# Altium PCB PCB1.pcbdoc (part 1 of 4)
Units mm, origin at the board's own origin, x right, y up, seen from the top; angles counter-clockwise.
Board outline 94.87 x 122.3 mm, 4 copper layers (Top Layer, Inner1, Inner2, Bottom Layer); 129 components, 127 nets, 714 pads, 326 vias.
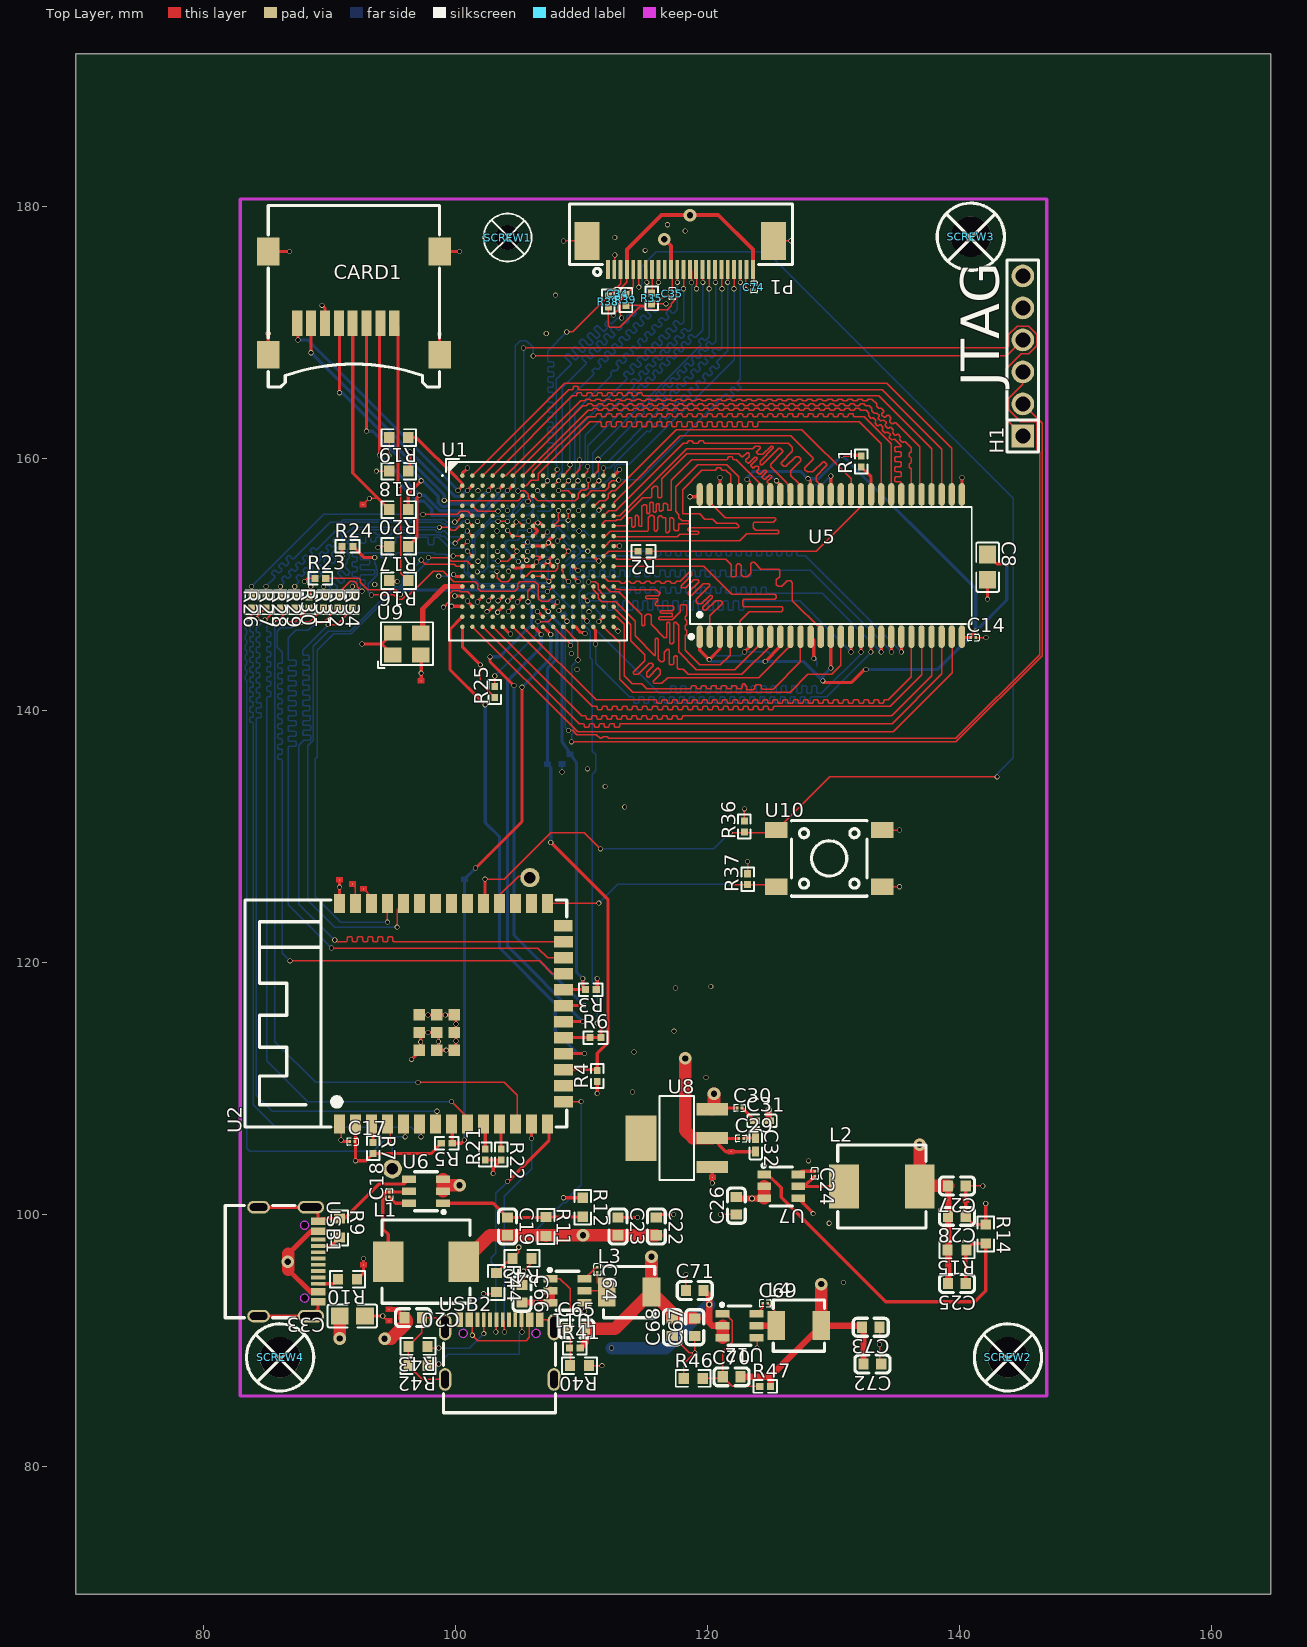
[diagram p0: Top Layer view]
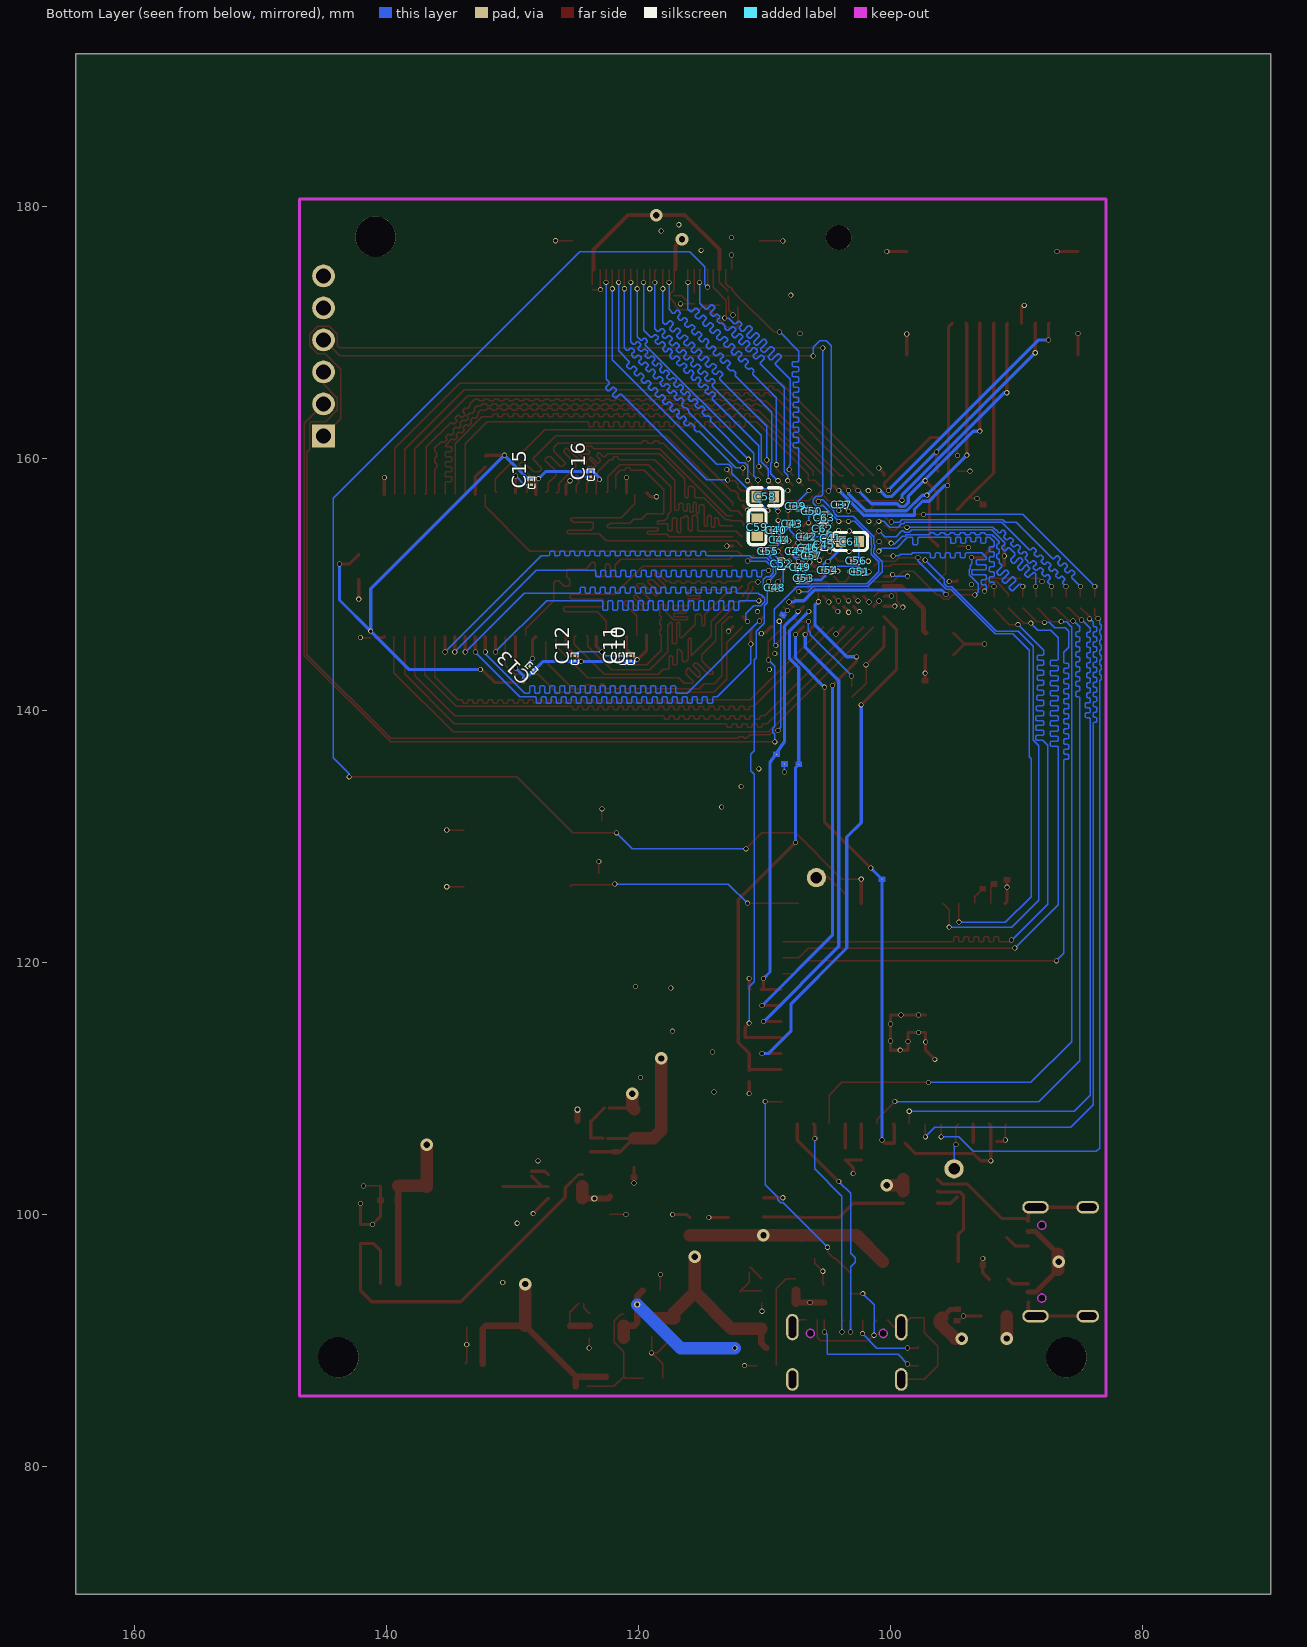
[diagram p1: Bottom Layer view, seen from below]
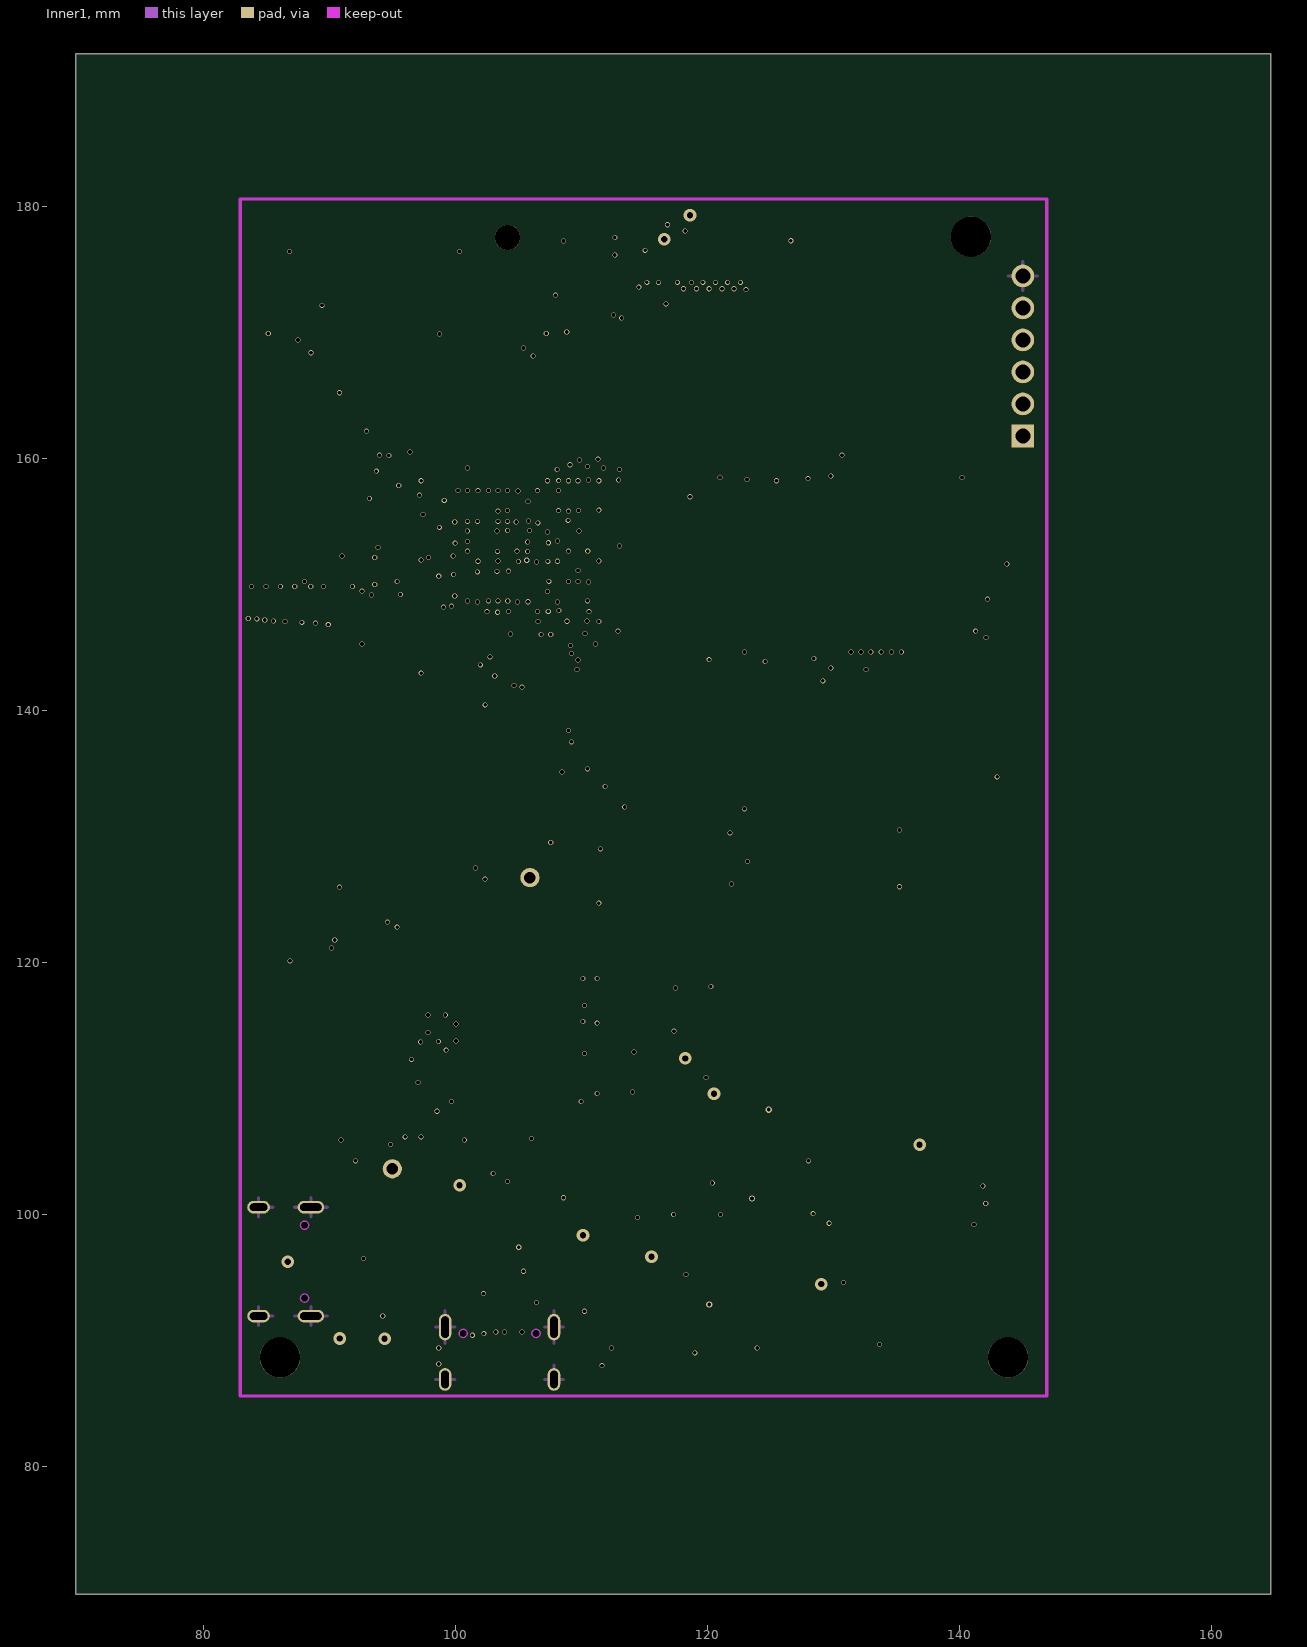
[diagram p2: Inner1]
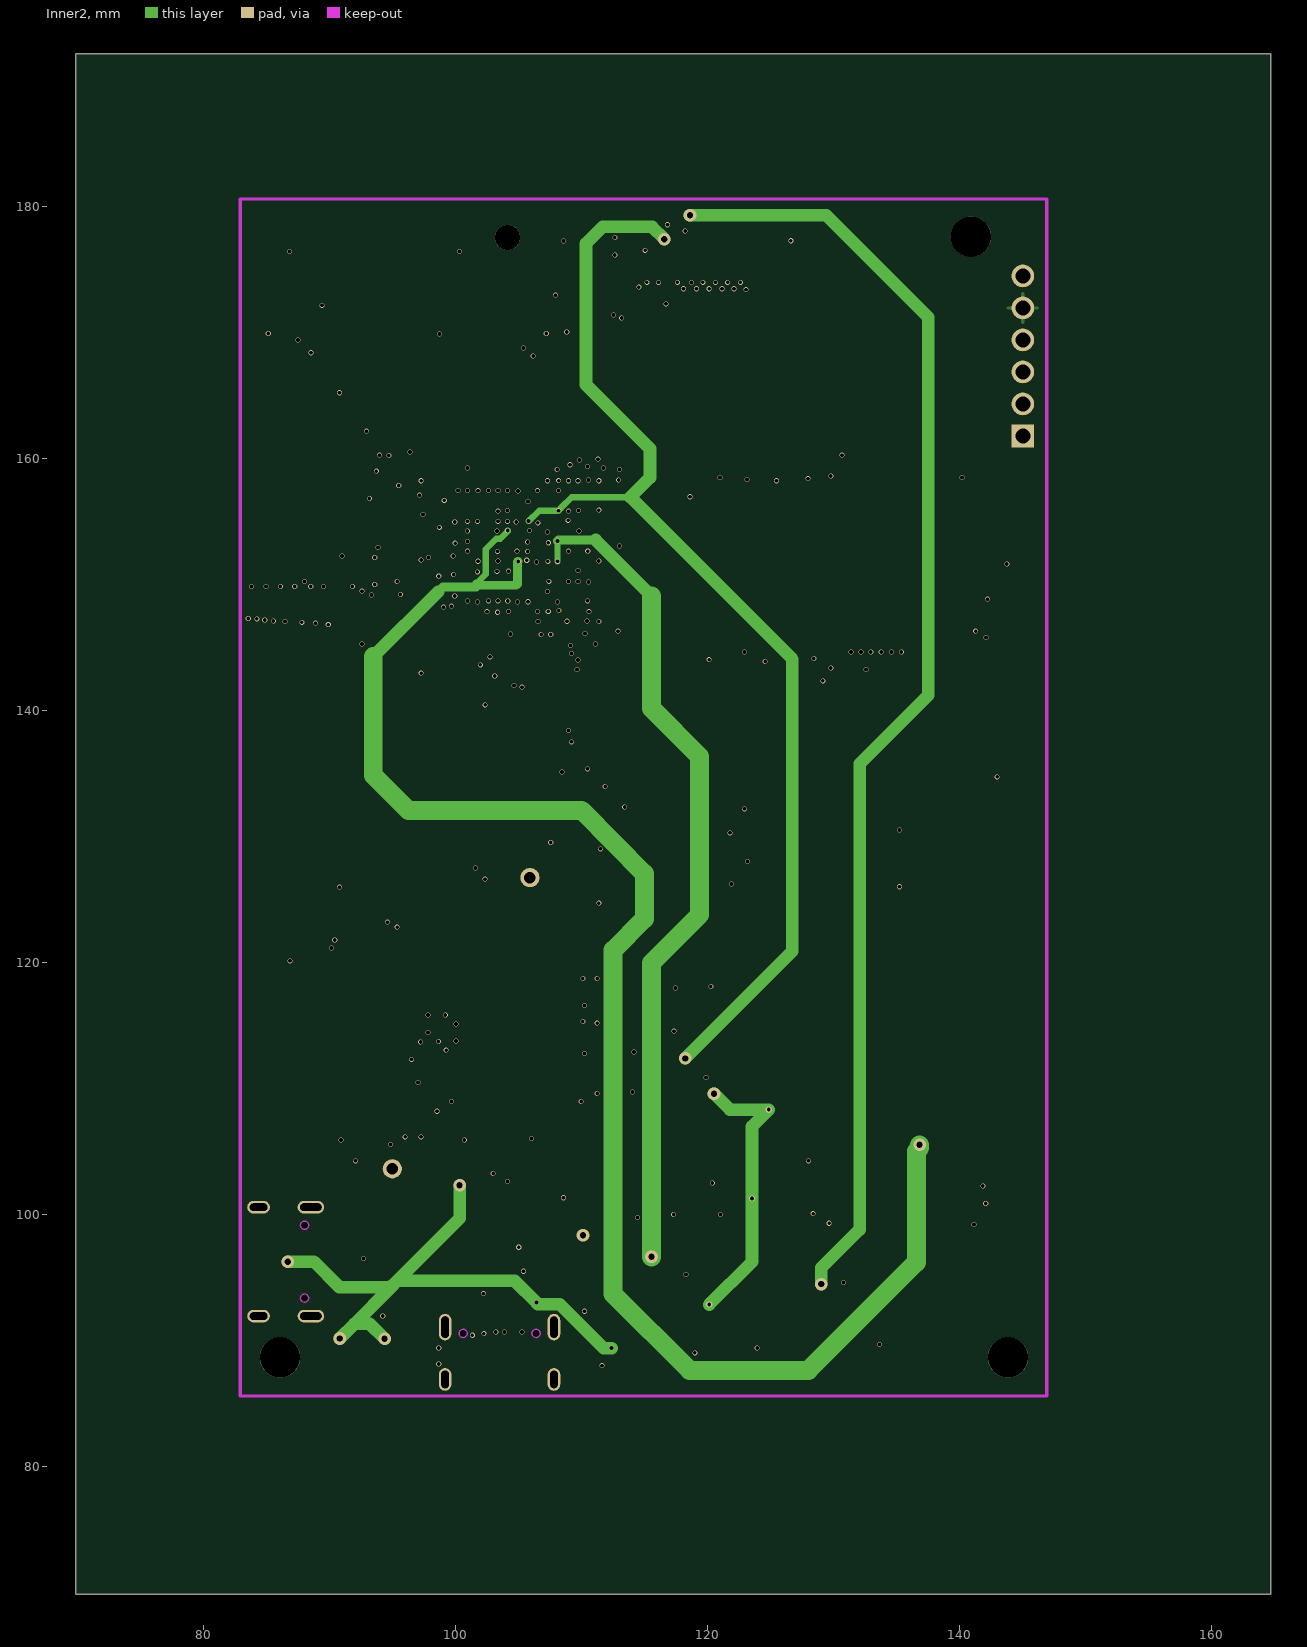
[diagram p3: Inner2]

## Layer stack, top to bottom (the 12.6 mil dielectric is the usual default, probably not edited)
Top Layer: signal copper (thickness not stored)
Dielectric: dielectric 0.32, FR-4, Dk 4.8
Inner1: signal copper (thickness not stored)
Dielectric: dielectric 0.32, FR-4, Dk 4.8
Inner2: signal copper (thickness not stored)
Dielectric: dielectric 0.32, FR-4, Dk 4.8
Bottom Layer: signal copper (thickness not stored)

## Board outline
164.719,69.85 69.85,69.85 69.85,192.151 164.719,192.151

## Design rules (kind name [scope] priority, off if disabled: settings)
BoardOutlineClearance copperThickness1oz [All] p0: genericclearance=0.254 ignorepadtopadclearanceinfootprint=FALSE except(0: Arc-SplitContinuation Track-SplitContinuation SMDPad-SplitContinuation THPad-SplitContinuation Via-SplitContinuation Fill-SplitContinuation Poly-SplitContinuation Region-SplitContinuation Text-SplitContinuation; 0.152: Track-CutoutEdge SMDPad-CutoutEdge THPad-CutoutEdge Via-CutoutEdge Region-CutoutEdge; 0.3: Track-OutlineEdge SMDPad-OutlineEdge THPad-OutlineEdge Via-OutlineEdge Fill-OutlineEdge Region-OutlineEdge Poly-OutlineEdge Text-OutlineEdge Fill-CutoutEdge)
BoardOutlineClearance copperThickness2oz [All] p0: genericclearance=0.254 ignorepadtopadclearanceinfootprint=FALSE except(0: Arc-SplitContinuation Track-SplitContinuation SMDPad-SplitContinuation THPad-SplitContinuation Via-SplitContinuation Fill-SplitContinuation Poly-SplitContinuation Region-SplitContinuation Text-SplitContinuation; 0.152: Track-CutoutEdge SMDPad-CutoutEdge THPad-CutoutEdge Via-CutoutEdge Region-CutoutEdge; 0.3: Track-OutlineEdge SMDPad-OutlineEdge THPad-OutlineEdge Via-OutlineEdge Fill-OutlineEdge Region-OutlineEdge Poly-OutlineEdge Text-OutlineEdge Fill-CutoutEdge)
Clearance copperThickness1oz [(InNet('SD_A0') OR InNet('SD_A1') OR InNet('SD_A2') OR InNet('SD_A3') OR InNet('SD_A4') OR InNet('SD_A5') OR InNet('SD_A6') OR InNet('SD_A7') OR InNet('SD_A8') OR InNet('SD_A9') OR InNet('SD_A10') OR InNet('SD_A11') OR InNet('SD_A12') OR InNet('SD_DQ15') OR InNet('SD_DQ14') OR InNet('SD_DQ8') OR InNet('SD_BA0') OR InNet('SD_BA1') OR InNet('SD_DQ9') OR InNet('SD_DQ7') OR InNet('SD_CLK') OR InNet('SD_WE_N') OR InNet('SD_DQ10') OR InNet('SD_CAS_N') OR InNet('SD_DQM1') OR InNet('SD_DQ2') OR InNet('SD_DQ3') OR InNet('SD_DQ11') OR InNet('SD_DQ12') OR InNet('SD_DQ13') OR InNet('SD_DQ0') OR InNet('SD_DQ1') OR InNet('SD_CS_N') OR InNet('SD_RAS_N') OR InNet('SD_DQ4') OR InNet('SD_DQ6') OR InNet('GND') OR InNet('SD_DQ5') OR InNet('SD_DQM0') OR InNet('$1N9437') OR InNet('+3V3') OR InNet('$1N11348') OR InNet('DOUT') OR InNet('DIN') OR InNet('CCLK') OR InNet('DONE') OR InNet('PROGRAMN') OR InNet('INITN') OR InNet('$1N11975') OR InNet('DN') OR InNet('DP') OR InNet('$1N14459') OR InNet('$1N14416') OR InNet('$1N14567') OR InNet('+5V') OR InNet('$1N16833') OR InNet('$1N16832') OR InNet('+1V1') OR InNet('$1N16834') OR InNet('+1V8') OR InNet('$1N17349') OR InNet('$1N12557') OR InNet('$1N12553') OR InNet('M_D2') OR InNet('M_D3') OR InNet('M_CMD') OR InNet('M_CLK') OR InNet('M_D0') OR InNet('M_D1') OR InNet('SDA') OR InNet('SCL') OR InNet('RESET') OR InNet('VSYNC') OR InNet('HREF') OR InNet('Y9') OR InNet('MCLK') OR InNet('Y8') OR InNet('Y7') OR InNet('PCLK') OR InNet('Y6') OR InNet('Y2') OR InNet('Y5') OR InNet('Y3') OR InNet('Y4') OR InNet('CRYSTAL') OR InNet('SSPI_CS_N') OR InNet('D0') OR InNet('D1') OR InNet('D2') OR InNet('D4') OR InNet('D3') OR InNet('D5') OR InNet('D6') OR InNet('D7') OR InNet('RX') OR InNet('TX') OR InNet('$1N29790') OR InNet('$1N29833') OR InNet('$1N29916') OR InNet('$1N29959') OR InNet('$1N30002') OR InNet('$1N30085') OR InNet('$1N30089') OR InNet('$1N30093') OR InNet('TDO') OR InNet('TDI') OR InNet('TMS') OR InNet('TCK') OR InNet('$1N33205') OR InNet('PROGRAM') OR InNet('$2N5507') OR InNet('$2N5509') OR InNet('$2N5511') OR InNet('FSDA') OR InNet('FSCL') OR InNet('+2V5') OR InNet('$1N60668') OR InNet('$1N60669') OR InNet('$1N60670') OR InNet('USB_VBUS') OR InNet('$1N63772') OR InNet('$1N63749') OR InNet('$1N63825') OR InNet('+2V8') OR InNet('$1N64402') OR InNet('$1N64401') OR InNet('$1N64403'))] p1: gap=0.178 ignorepadtopadclearanceinfootprint=FALSE except(0.099: Track-Track; 0.152: Track-SMDPad SMDPad-SMDPad Track-THPad SMDPad-THPad THPad-THPad Track-Via SMDPad-Via THPad-Via Via-Via SMDPad-Fill THPad-Fill Via-Fill Fill-Fill Track-Region SMDPad-Region THPad-Region Via-Region Region-Region Track-Poly SMDPad-Poly THPad-Poly Via-Poly Fill-Poly Region-Poly Poly-Poly Track-Text SMDPad-Text THPad-Text Via-Text Fill-Text Region-Text Poly-Text Text-Text; 0.175: Track-Hole SMDPad-Hole THPad-Hole Via-Hole Fill-Hole Region-Hole Poly-Hole Text-Hole Sheet-Hole; 0.3: Track-Fill Fill-Region Track-Sheet SMDPad-Sheet THPad-Sheet Via-Sheet Fill-Sheet Region-Sheet Poly-Sheet Text-Sheet)
Clearance copperThickness2oz [All] p1: gap=0.178 ignorepadtopadclearanceinfootprint=FALSE except(0.152: Track-SMDPad SMDPad-SMDPad Track-THPad SMDPad-THPad THPad-THPad Track-Via SMDPad-Via THPad-Via Via-Via SMDPad-Fill THPad-Fill Via-Fill Fill-Fill Track-Region SMDPad-Region THPad-Region Via-Region Region-Region Track-Poly SMDPad-Poly THPad-Poly Via-Poly Fill-Poly Region-Poly Poly-Poly Track-Text SMDPad-Text THPad-Text Via-Text Fill-Text Region-Text Poly-Text Text-Text; 0.175: Track-Hole SMDPad-Hole THPad-Hole Via-Hole Fill-Hole Region-Hole Poly-Hole Text-Hole Sheet-Hole; 0.203: Track-Track; 0.3: Track-Fill Fill-Region Track-Sheet SMDPad-Sheet THPad-Sheet Via-Sheet Fill-Sheet Region-Sheet Poly-Sheet Text-Sheet)
DiffPairsRouting differentialPair [All] p1: maxuncoupledlength=10 minlimit=6 maxlimit=6 mostfreqgap=6 toplayer_minwidth=5 toplayer_prefwidth=10 toplayer_maxwidth=100 bottomlayer_minwidth=5 bottomlayer_prefwidth=10 bottomlayer_maxwidth=100 midlayer1_minwidth=5 midlayer1_prefwidth=10 midlayer1_maxwidth=100 midlayer2_minwidth=5 midlayer2_prefwidth=10 midlayer2_maxwidth=100
PasteMaskExpansion pasteMaskExpansion [All] p1: expansion=0
PlaneConnect innerPlane [All] p1: planeconnectstyle=Relief reliefexpansion=0.508 reliefentries=4 reliefconductorwidth=0.254 reliefairgap=0.254
PolygonConnect copperRegion [All] p1: connectstyle=Relief reliefentries=4 reliefconductorwidth=10 polygonreliefangle="90 Angle" airgapwidth=10
RoutingVias viaSize [All] p1: viastyle="Through Hole" holewidth=11.811 minholewidth=11.811 maxholewidth=248.0314 width=15.748 minwidth=15.748 maxwidth=393.7008
SolderMaskExpansion solderMaskExpansion [All] p1: useseparateexpansions=TRUE expansion=2 expansionbottom=2
Width copperThickness1oz [All] p1: maxlimit=100 minlimit=4 preferedwidth=4
Width copperThickness2oz [All] p1: maxlimit=100 minlimit=8 preferedwidth=10

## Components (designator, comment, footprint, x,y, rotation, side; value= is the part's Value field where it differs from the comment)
C8 "CL21A476MQYNNNE" C0805 142.24,151.384 r270 top
C10 "GRM022R60J104KE15D" C01005 120.65,144.145 r90 bottom
C11 "GRM022R60J104KE15D" C01005 121.285,144.145 r90 bottom
C12 "GRM022R60J104KE15D" C01005 125.095,144.145 r90 bottom
C13 "GRM022R60J104KE15D" C01005 128.524,143.383 r45 bottom
C14 "GRM022R60J104KE15D" C01005 141.097,145.796 r0 top
C15 "GRM022R60J104KE15D" C01005 128.524,158.115 r90 bottom
C16 "GRM022R60J104KE15D" C01005 123.825,158.75 r90 bottom
C17 "GRM022R60J104KE15D" C01005 91.821,105.791 r0 top
C18 "GRM022R60J104KE15D" C01005 94.742,101.6 r90 top
C19 "TCC0603X7R104K500CT" C0603 104.14,99.06 r270 top
C20 "TCC0603X5R226M6R3CT" C0603 96.647,91.821 r180 top
C22 "TCC0603X5R226M6R3CT" C0603 115.951,99.06 r270 top
C23 "TCC0603X5R226M6R3CT" C0603 112.903,99.06 r270 top
C24 "GRM022R60J104KE15D" C01005 128.524,103.251 r270 top
C25 "TCC0603X7R104K500CT" C0603 139.806,94.527 r180 top
C26 "TCC0603X5R226M6R3CT" C0603 122.301,100.711 r90 top
C27 "TCC0603X5R226M6R3CT" C0603 139.806,102.274 r180 top
C28 "TCC0603X5R226M6R3CT" C0603 139.806,99.861 r180 top
C29 "GRM022R60J104KE15D" C01005 122.682,106.045 r0 top
C30 "GRM022R60J104KE15D" C01005 122.555,108.458 r0 top
C31 "GRM155R60J106ME44D" C0402 124.333,107.442 r0 top
C32 "GRM155R60J106ME44D" C0402 123.825,105.537 r270 top
C33 "CL21A476MQYNNNE" C0805 91.821,91.948 r180 top
C34 "GRM022R60J104KE15D" C01005 112.903,173.101 r270 top
C35 "GRM022R60J104KE15D" C01005 117.221,173.101 r270 top
C37 "GRM022R60J104KE15D" C01005 103.886,156.337 r180 bottom
C39 "GRM022R60J104KE15D" C01005 107.569,156.21 r180 bottom
C40 "GRM022R60J104KE15D" C01005 109.093,154.305 r180 bottom
C41 "GRM022R60J104KE15D" C01005 104.775,153.67 r90 bottom
C42 "GRM022R60J104KE15D" C01005 106.68,153.797 r180 bottom
C43 "GRM022R60J104KE15D" C01005 107.823,154.813 r180 bottom
C44 "GRM022R60J104KE15D" C01005 108.839,153.543 r180 bottom
C45 "GRM022R60J104KE15D" C01005 105.283,153.162 r270 bottom
C46 "GRM022R60J104KE15D" C01005 106.553,152.908 r180 bottom
C47 "GRM022R60J104KE15D" C01005 107.569,152.654 r0 bottom
C48 "GRM022R60J104KE15D" C01005 109.22,149.733 r180 bottom
C49 "GRM022R60J104KE15D" C01005 107.188,151.384 r180 bottom
C50 "GRM022R60J104KE15D" C01005 106.299,155.829 r180 bottom
C51 "GRM022R60J104KE15D" C01005 102.489,151.003 r180 bottom
C52 "GRM022R60J104KE15D" C01005 108.712,151.638 r270 bottom
C53 "GRM022R60J104KE15D" C01005 106.934,150.495 r180 bottom
C54 "GRM022R60J104KE15D" C01005 105.029,151.13 r180 bottom
C55 "GRM022R60J104KE15D" C01005 109.728,152.654 r0 bottom
C56 "GRM022R60J104KE15D" C01005 102.743,151.892 r180 bottom
C57 "GRM022R60J104KE15D" C01005 106.299,152.273 r0 bottom
C58 "TCC0603X5R226M6R3CT" C0603 109.982,156.972 r180 bottom
C59 "TCC0603X5R226M6R3CT" C0603 110.617,154.559 r90 bottom
C61 "TCC0603X5R226M6R3CT" C0603 103.251,153.416 r180 bottom
C62 "GRM022R60J104KE15D" C01005 105.41,154.432 r270 bottom
C63 "GRM022R60J104KE15D" C01005 105.283,155.321 r90 bottom
C64 "GRM022R60J104KE15D" C01005 111.252,95.631 r270 top
C65 "TCC0603X7R104K500CT" C0603 109.601,90.932 r0 top
C66 "TCC0603X5R226M6R3CT" C0603 105.283,93.726 r270 top
C67 "TCC0603X5R226M6R3CT" C0603 118.999,91.059 r90 top
C68 "TCC0603X5R226M6R3CT" C0603 117.221,91.059 r90 top
C69 "GRM022R60J104KE15D" C01005 124.587,92.964 r0 top
C70 "TCC0603X7R104K500CT" C0603 121.92,87.122 r0 top
C71 "TCC0603X5R226M6R3CT" C0603 118.999,93.98 r0 top
C72 "TCC0603X5R226M6R3CT" C0603 133.096,88.138 r180 top
C73 "TCC0603X5R226M6R3CT" C0603 132.969,91.059 r180 top
C74 "GRM022R60J104KE15D" C01005 123.698,173.609 r270 top
CARD1 "DS1139-06-08SS4BSR" TF-SMD_DS1139-06-08SS4BSR 91.948,172.339 r0 top
H1 "2.54-1x6P直针" HDR-TH_6P-P2.54-V-M-1 145.034,168.148 r90 top
L1 "FXL0630-6R8-M" IND-SMD_L7.0-W6.6 97.663,96.266 r0 top
L2 "FXL0630-100-M" IND-SMD_L7.3-W6.8 133.842,102.229 r0 top
L3 "SL0420-3R3M" IND-SMD_L4.5-W4.1_SL0420 113.792,93.853 r0 top
L4 "SL0420-3R3M" IND-SMD_L4.5-W4.1_SL0420 127.254,91.186 r0 top
P1 "AFC07-S24FCC-00" FPC-SMD_AFC07-S24FCC-00 117.856,176.149 r180 top
R1 "0402WGF1002TCE" R0402 132.207,159.766 r90 top
R2 "0402WGF330JTCE" R0402 114.935,152.654 r180 top
R3 "0402WGF1002TCE" R0402 110.744,117.856 r180 top
R4 "0402WGF1002TCE" R0402 111.252,110.998 r90 top
R5 "0402WGF1002TCE" R0402 99.314,105.664 r180 top
R6 "0402WGF330JTCE" R0402 111.125,114.046 r0 top
R7 "0402WGF1002TCE" R0402 93.472,105.283 r270 top
R9 "0603WAF5101T5E" R0603 90.805,98.933 r270 top
R10 "0603WAF5101T5E" R0603 91.44,94.869 r180 top
R11 "FRC0603F1963TS" R0603 107.188,99.06 r270 top
R12 "FRC0603F6202TS" R0603 110.109,100.584 r270 top
R14 "FRC0603F6202TS" R0603 142.092,98.464 r270 top
R15 "0603WAF2322T5E" R0603 139.806,97.194 r180 top
R16 "FRC0603F6202TS" R0603 95.5,150.317 r180 top
R17 "FRC0603F6202TS" R0603 95.504,153.035 r180 top
R18 "FRC0603F6202TS" R0603 95.504,159.004 r180 top
R19 "FRC0603F6202TS" R0603 95.504,161.671 r180 top
R20 "FRC0603F6202TS" R0603 95.504,155.956 r180 top
R21 "0402WGF1002TCE" R0402 102.362,104.775 r270 top
R22 "0402WGF1002TCE" R0402 103.632,104.775 r270 top
R23 "0402WGF1002TCE" R0402 89.281,150.495 r0 top
R24 "0402WGF1002TCE" R0402 91.44,153.035 r0 top
R25 "0402WGF1002TCE" R0402 103.124,141.478 r90 top
R26 "0402WGF330JTCE" R0402 83.82,148.59 r270 top
R27 "0402WGF330JTCE" R0402 84.963,148.59 r270 top
R28 "0402WGF330JTCE" R0402 86.106,148.59 r270 top
R29 "0402WGF330JTCE" R0402 87.249,148.59 r270 top
R30 "0402WGF330JTCE" R0402 88.392,148.59 r270 top
R31 "0402WGF330JTCE" R0402 89.535,148.59 r270 top
R32 "0402WGF330JTCE" R0402 90.678,148.59 r270 top
R34 "0402WGF330JTCE" R0402 91.821,148.59 r270 top
R35 "0402WGF1002TCE" R0402 115.57,172.72 r270 top
R36 "0402WGF1002TCE" R0402 122.936,130.81 r90 top
R37 "0402WGF1002TCE" R0402 123.19,126.619 r90 top
R38 "0402WGF1002TCE" R0402 112.141,172.466 r270 top
R39 "0402WGF1002TCE" R0402 113.538,172.593 r270 top
R40 "FRC0603F6202TS" R0603 109.855,88.011 r180 top
R41 "RC0402FR-07130KL" R0402 109.474,89.408 r0 top
R42 "0603WAF5101T5E" R0603 97.028,88.011 r180 top
R43 "0603WAF5101T5E" R0603 97.028,89.535 r180 top
R44 "FRC0603F1963TS" R0603 103.251,94.615 r270 top
R45 "FRC0603F1963TS" R0603 105.283,96.52 r180 top
R46 "FRC0603F6202TS" R0603 118.872,86.995 r0 top
R47 "0402WGF1543TCE" R0402 124.587,86.36 r0 top
SCREW1 "Screw-Hole-M2" Screw-Hole-M2 104.14,177.546 r0 top
SCREW2 "Screw-Hole-M3" Screw-Hole-M3 143.918,88.604 r0 top
SCREW3 "Screw-Hole-M3" Screw-Hole-M3 140.97,177.546 r0 top
SCREW4 "Screw-Hole-M3" Screw-Hole-M3 86.148,88.604 r0 top
U1 "LFE5U-25F-6BG256C" CABGA-256_L14.0-W14.0-R16-C16-P0.80-TL 106.553,152.654 r0 top
U2 "ESP32-S3-WROOM-1-N16R2" WIRELM-SMD_ESP32-S3-WROOM-1 99.695,115.951 r90 top
U5 "W9825G6KH-6" TSOP-54_L22.2-W10.2-P0.80-LS11.8-BL 129.794,151.511 r0 top
U6 "AP63200WU-7" SOT-23-6_L2.9-W1.6-P0.95-LS2.8-BR 97.663,101.854 r0 top
U7 "AP63200WU-7" SOT-23-6_L2.9-W1.6-P0.95-LS2.8-BR 125.857,102.235 r180 top
U8 "AMS1117-1.8_C6185" SOT-223-4_L6.5-W3.5-P2.30-LS7.0-BR 117.555,106.074 r0 top
U9 "XOS32024000LT00351005" OSC-SMD_4P-L3.2-W2.5-BL 96.139,145.288 r0 top
U10 "TPS645-5NC60" SW-SMD_4P-L6.0-W6.0-P4.50-LS9.2 129.667,128.27 r0 top
U11 "AP63200WU-7" SOT-23-6_L2.9-W1.6-P0.95-LS2.8-BR 108.892,93.952 r180 top
U12 "AP63200WU-7" SOT-23-6_L2.9-W1.6-P0.95-LS2.8-BR 122.555,91.186 r180 top
USB1 "TYPE-C16PIN" USB-C-SMD_TYPE-C16PIN#1 86.741,96.266 r270 top
USB2 "TYPE-C16PIN" USB-C-SMD_TYPE-C16PIN#2 103.505,89.281 r0 top

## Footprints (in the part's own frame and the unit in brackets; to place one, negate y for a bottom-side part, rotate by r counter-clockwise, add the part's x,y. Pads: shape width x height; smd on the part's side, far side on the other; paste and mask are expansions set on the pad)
C0402 [mm]
  rect 0.79x0.54 smd: 1(-0.545,0) 2(0.545,0)
  silkscreen extent -1.17,-0.5 1.17,0.5
C0603 [mm]
  rect 0.8x0.9 smd: 1(-0.7,0) 2(0.7,0)
  silkscreen extent -1.39,-0.71 1.39,0.71
C0805 [mm]
  rect 1.41x1.35 smd: 1(-1,0) 2(1,0)
  silkscreen extent -1.96,-0.9 1.96,0.9
C01005 [mm]
  rect 0.21x0.22 smd: 1(-0.195,0) 2(0.195,0)
  silkscreen extent -0.46,-0.27 0.46,0.27
CABGA-256_L14.0-W14.0-R16-C16-P0.80-TL [mm]
  round 0.36 smd: A1(-6,6) A2(-5.2,6) A3(-4.4,6) A4(-3.6,6) A5(-2.8,6) A6(-2,6) A7(-1.2,6) A8(-0.4,6) A9(0.4,6) A10(1.2,6) A11(2,6) A12(2.8,6) A13(3.6,6) A14(4.4,6) A15(5.2,6) A16(6,6) B1(-6,5.2) B2(-5.2,5.2) B3(-4.4,5.2) B4(-3.6,5.2) B5(-2.8,5.2) B6(-2,5.2) B7(-1.2,5.2) B8(-0.4,5.2) B9(0.4,5.2) B10(1.2,5.2) B11(2,5.2) B12(2.8,5.2) B13(3.6,5.2) B14(4.4,5.2) B15(5.2,5.2) B16(6,5.2) C1(-6,4.4) C2(-5.2,4.4) C3(-4.4,4.4) C4(-3.6,4.4) C5(-2.8,4.4) C6(-2,4.4) C7(-1.2,4.4) C8(-0.4,4.4) C9(0.4,4.4) C10(1.2,4.4) C11(2,4.4) C12(2.8,4.4) C13(3.6,4.4) C14(4.4,4.4) C15(5.2,4.4) C16(6,4.4) D1(-6,3.6) D2(-5.2,3.6) D3(-4.4,3.6) D4(-3.6,3.6) D5(-2.8,3.6) D6(-2,3.6) D7(-1.2,3.6) D8(-0.4,3.6) D9(0.4,3.6) D10(1.2,3.6) D11(2,3.6) D12(2.8,3.6) D13(3.6,3.6) D14(4.4,3.6) D15(5.2,3.6) D16(6,3.6) E1(-6,2.8) E2(-5.2,2.8) E3(-4.4,2.8) E4(-3.6,2.8) E5(-2.8,2.8) E6(-2,2.8) E7(-1.2,2.8) E8(-0.4,2.8) E9(0.4,2.8) E10(1.2,2.8) E11(2,2.8) E12(2.8,2.8) E13(3.6,2.8) E14(4.4,2.8) E15(5.2,2.8) E16(6,2.8) F1(-6,2) F2(-5.2,2) F3(-4.4,2) F4(-3.6,2) F5(-2.8,2) F6(-2,2) F7(-1.2,2) F8(-0.4,2) F9(0.4,2) F10(1.2,2) F11(2,2) F12(2.8,2) F13(3.6,2) F14(4.4,2) F15(5.2,2) F16(6,2) G1(-6,1.2) G2(-5.2,1.2) G3(-4.4,1.2) G4(-3.6,1.2) G5(-2.8,1.2) G6(-2,1.2) G7(-1.2,1.2) G8(-0.4,1.2) G9(0.4,1.2) G10(1.2,1.2) G11(2,1.2) G12(2.8,1.2) G13(3.6,1.2) G14(4.4,1.2) G15(5.2,1.2) G16(6,1.2) H1(-6,0.4) H2(-5.2,0.4) H3(-4.4,0.4) H4(-3.6,0.4) H5(-2.8,0.4) H6(-2,0.4) H7(-1.2,0.4) H8(-0.4,0.4) H9(0.4,0.4) H10(1.2,0.4) H11(2,0.4) H12(2.8,0.4) H13(3.6,0.4) H14(4.4,0.4) H15(5.2,0.4) H16(6,0.4) J1(-6,-0.4) J2(-5.2,-0.4) J3(-4.4,-0.4) J4(-3.6,-0.4) J5(-2.8,-0.4) J6(-2,-0.4) J7(-1.2,-0.4) J8(-0.4,-0.4) J9(0.4,-0.4) J10(1.2,-0.4) J11(2,-0.4) J12(2.8,-0.4) J13(3.6,-0.4) J14(4.4,-0.4) J15(5.2,-0.4) J16(6,-0.4) K1(-6,-1.2) K2(-5.2,-1.2) K3(-4.4,-1.2) K4(-3.6,-1.2) K5(-2.8,-1.2) K6(-2,-1.2) K7(-1.2,-1.2) K8(-0.4,-1.2) K9(0.4,-1.2) K10(1.2,-1.2) K11(2,-1.2) K12(2.8,-1.2) K13(3.6,-1.2) K14(4.4,-1.2) K15(5.2,-1.2) K16(6,-1.2) L1(-6,-2) L2(-5.2,-2) L3(-4.4,-2) L4(-3.6,-2) L5(-2.8,-2) L6(-2,-2) L7(-1.2,-2) L8(-0.4,-2) L9(0.4,-2) L10(1.2,-2) L11(2,-2) L12(2.8,-2) L13(3.6,-2) L14(4.4,-2) L15(5.2,-2) L16(6,-2) M1(-6,-2.8) M2(-5.2,-2.8) M3(-4.4,-2.8) M4(-3.6,-2.8) M5(-2.8,-2.8) M6(-2,-2.8) M7(-1.2,-2.8) M8(-0.4,-2.8) M9(0.4,-2.8) M10(1.2,-2.8) M11(2,-2.8) M12(2.8,-2.8) M13(3.6,-2.8) M14(4.4,-2.8) M15(5.2,-2.8) M16(6,-2.8) N1(-6,-3.6) N2(-5.2,-3.6) N3(-4.4,-3.6) N4(-3.6,-3.6) N5(-2.8,-3.6) N6(-2,-3.6) N7(-1.2,-3.6) N8(-0.4,-3.6) N9(0.4,-3.6) N10(1.2,-3.6) N11(2,-3.6) N12(2.8,-3.6) N13(3.6,-3.6) N14(4.4,-3.6) N15(5.2,-3.6) N16(6,-3.6) P1(-6,-4.4) P2(-5.2,-4.4) P3(-4.4,-4.4) P4(-3.6,-4.4) P5(-2.8,-4.4) P6(-2,-4.4) P7(-1.2,-4.4) P8(-0.4,-4.4) P9(0.4,-4.4) P10(1.2,-4.4) P11(2,-4.4) P12(2.8,-4.4) P13(3.6,-4.4) P14(4.4,-4.4) P15(5.2,-4.4) P16(6,-4.4) R1(-6,-5.2) R2(-5.2,-5.2) R3(-4.4,-5.2) R4(-3.6,-5.2) R5(-2.8,-5.2) R6(-2,-5.2) R7(-1.2,-5.2) R8(-0.4,-5.2) R9(0.4,-5.2) R10(1.2,-5.2) R11(2,-5.2) R12(2.8,-5.2) R13(3.6,-5.2) R14(4.4,-5.2) R15(5.2,-5.2) R16(6,-5.2) T1(-6,-6) T2(-5.2,-6) T3(-4.4,-6) T4(-3.6,-6) T5(-2.8,-6) T6(-2,-6) T7(-1.2,-6) T8(-0.4,-6) T9(0.4,-6) T10(1.2,-6) T11(2,-6) T12(2.8,-6) T13(3.6,-6) T14(4.4,-6) T15(5.2,-6) T16(6,-6)
  silkscreen extent -7.63,-7.08 7.08,7.3
FPC-SMD_AFC07-S24FCC-00 [mm]
  rect 0.3x1.5 smd: 1(5.745,1.129) 2(5.245,1.129) 3(4.746,1.129) 4(4.245,1.129) 5(3.746,1.129) 6(3.245,1.129) 7(2.746,1.129) 8(2.245,1.129) 9(1.746,1.129) 10(1.245,1.129) 11(0.746,1.129) 12(0.245,1.129) 13(-0.254,1.129) 14(-0.755,1.129) 15(-1.251,1.13) 16(-1.754,1.13) 17(-2.254,1.128) 18(-2.754,1.129) 19(-3.254,1.129) 20(-3.756,1.132) 21(-4.256,1.132) 22(-4.756,1.132) 23(-5.256,1.132) 24(-5.756,1.132)
  rect 2x3 smd: 25(-7.401,-1.132) 26(7.401,-1.125)
  silkscreen extent -8.89,-4.07 8.8,1.61
HDR-TH_6P-P2.54-V-M-1 [mm]
  rect 1.8x1.8 hole 1.2: 1(-6.35,0)
  round 1.8 hole 1.2: 2(-3.81,0) 3(-1.27,0) 4(1.27,0) 5(3.81,0) 6(6.35,0)
  silkscreen extent -7.62,-1.25 7.62,1.25
IND-SMD_L4.5-W4.1_SL0420 [mm]
  rect 1.4x2.3 smd: 1(-1.775,0) 2(1.775,0)
  silkscreen extent -2.03,-2.03 2.03,2.03
IND-SMD_L7.0-W6.6 [mm]
  rect 2.4x3.2 smd: 1(-3,0) 2(3,0)
  silkscreen extent -3.5,-3.3 3.5,3.3
IND-SMD_L7.3-W6.8 [mm]
  rect 2.35x3.5 smd: 1(-3,0) 2(3,0)
  silkscreen extent -3.5,-3.3 3.5,3.3
OSC-SMD_4P-L3.2-W2.5-BL [mm]
  rect 1.4x1.2 smd: 1(-1.1,-0.875) 2(1.1,-0.875) 3(1.1,0.875) 4(-1.1,0.875)
  silkscreen extent -2.29,-1.9 2.07,1.72
R0402 [mm]
  rect 0.566x0.54 smd: 1(-0.433,0) 2(0.433,0)
  silkscreen extent -0.94,-0.5 0.94,0.5
R0603 [mm]
  rect 0.806x0.864 smd: 1(-0.753,0) 2(0.753,0)
  silkscreen extent -1.39,-0.66 1.39,0.66
Screw-Hole-M2 [mm]
  round 2 hole 2: 1(0,0)
  silkscreen extent -1.9,-1.9 1.9,1.9
Screw-Hole-M3 [mil]
  round 126 hole 126: 1(-2.5,2.5)
  silkscreen extent -107,-102 102,107
SOT-23-6_L2.9-W1.6-P0.95-LS2.8-BR [mm]
  rect 1.1x0.6 smd: 1(1.35,-0.95) 2(1.35,0) 3(1.35,0.95) 4(-1.35,0.95) 5(-1.35,0) 6(-1.35,-0.95)
  silkscreen extent -0.9,-1.78 1.52,1.55
SOT-223-4_L6.5-W3.5-P2.30-LS7.0-BR [mm]
  rect 2.47x0.98 smd: 1(2.835,-2.3) 2(2.835,0) 3(2.835,2.3)
  rect 2.47x3.6 smd: 4(-2.835,0)
  silkscreen extent -1.37,-3.33 1.37,3.33
SW-SMD_4P-L6.0-W6.0-P4.50-LS9.2 [mm]
  rect 1.8x1.3 smd: 1(-4.2,2.25) 2(4.2,2.25) 3(-4.2,-2.25) 4(4.2,-2.25)
  silkscreen extent -3,-3 3,3
TF-SMD_DS1139-06-08SS4BSR [mm]
  rect 0.8x2 smd: 1(3.2,-1.6) 2(2.1,-1.6) 3(1,-1.6) 4(-0.1,-1.6) 5(-1.2,-1.6) 6(-2.3,-1.6) 7(-3.4,-1.6) 8(-4.5,-1.6)
  rect 1.8x2.2 smd: 9(-6.8,4.1) 10(-6.8,-4.1) 11(6.8,-4.1) 12(6.8,4.1)
  silkscreen extent -6.8,-6.65 6.8,7.75
TSOP-54_L22.2-W10.2-P0.80-LS11.8-BL [mm]
  oval 0.5x1.8 smd: 1(-10.4,-5.642) 2(-9.6,-5.642) 3(-8.8,-5.642) 4(-8,-5.642) 5(-7.2,-5.642) 6(-6.4,-5.642) 7(-5.6,-5.642) 8(-4.8,-5.642) 9(-4,-5.642) 10(-3.2,-5.642) 11(-2.4,-5.642) 12(-1.6,-5.642) 13(-0.8,-5.642) 14(0,-5.642) 15(0.8,-5.642) 16(1.6,-5.642) 17(2.4,-5.642) 18(3.2,-5.642) 19(4,-5.642) 20(4.8,-5.642) 21(5.6,-5.642) 22(6.4,-5.642) 23(7.2,-5.642) 24(8,-5.642) 25(8.8,-5.642) 26(9.6,-5.642) 27(10.4,-5.642) 28(10.4,5.642) 29(9.6,5.642) 30(8.8,5.642) 31(8,5.642) 32(7.2,5.642) 33(6.4,5.642) 34(5.6,5.642) 35(4.8,5.642) 36(4,5.642) 37(3.2,5.642) 38(2.4,5.642) 39(1.6,5.642) 40(0.8,5.642) 41(0,5.642) 42(-0.8,5.642) 43(-1.6,5.642) 44(-2.4,5.642) 45(-3.2,5.642) 46(-4,5.642) 47(-4.8,5.642) 48(-5.6,5.642) 49(-6.4,5.642) 50(-7.2,5.642) 51(-8,5.642) 52(-8.8,5.642) 53(-9.6,5.642) 54(-10.4,5.642)
  silkscreen extent -11.23,-5.79 11.19,4.65
USB-C-SMD_TYPE-C16PIN#1 [mm]
  oval 1x2.1 hole 0.6 slot 1.7 at 90 deg: 1(-4.32,1.787) 2(4.32,1.787)
  oval 1x1.8 hole 0.6 slot 1.4 at 90 deg: 3(-4.32,-2.362) 4(4.32,-2.362)
  rect 0.6x1.15 smd: A1B12(-3.2,2.362) A4B9(-2.4,2.362) B1A12(3.2,2.362) B4A9(2.4,2.362)
  rect 0.3x1.15 smd: A5(-1.25,2.362) A6(-0.25,2.362) A7(0.25,2.362) A8(1.25,2.362) B5(1.75,2.362) B6(0.75,2.362) B7(-0.75,2.362) B8(-1.75,2.362)
  Board Outline Layer circle w0.005: c2.89,1.288 r0.325
  Board Outline Layer circle w0.005: c-2.89,1.288 r0.325
  Board Outline Layer region: 2.89,1.613 3.031,1.581 3.144,1.491 3.207,1.36 3.207,1.216 3.144,1.085 3.031,0.995 2.89,0.963 2.89,0.963 2.749,0.995 2.636,1.085 2.573,1.216 2.573,1.36 2.636,1.491 2.749,1.581 2.89,1.613
  Board Outline Layer region: -2.89,1.613 -2.749,1.581 -2.636,1.491 -2.573,1.36 -2.573,1.216 -2.636,1.085 -2.749,0.995 -2.89,0.963 -2.89,0.963 -3.031,0.995 -3.144,1.085 -3.207,1.216 -3.207,1.36 -3.144,1.491 -3.031,1.581 -2.89,1.613
  Multi-Layer board cut-out: 2.89,1.613 3.031,1.581 3.144,1.491 3.207,1.36 3.207,1.216 3.144,1.085 3.031,0.995 2.89,0.963 2.89,0.963 2.749,0.995 2.636,1.085 2.573,1.216 2.573,1.36 2.636,1.491 2.749,1.581 2.89,1.613
  Multi-Layer board cut-out: -2.89,1.613 -2.749,1.581 -2.636,1.491 -2.573,1.36 -2.573,1.216 -2.636,1.085 -2.749,0.995 -2.89,0.963 -2.89,0.963 -3.031,0.995 -3.144,1.085 -3.207,1.216 -3.207,1.36 -3.144,1.491 -3.031,1.581 -2.89,1.613
  silkscreen extent -4.45,-5 4.45,0.52
USB-C-SMD_TYPE-C16PIN#2 [mm]
  oval 1x2.1 hole 0.6 slot 1.7 at 90 deg: 1(-4.32,1.787) 2(4.32,1.787)
  oval 1x1.8 hole 0.6 slot 1.4 at 90 deg: 3(-4.32,-2.362) 4(4.32,-2.362)
  rect 0.6x1.15 smd: A1B12(-3.2,2.362) A4B9(-2.4,2.362) B1A12(3.2,2.362) B4A9(2.4,2.362)
  rect 0.3x1.15 smd: A5(-1.25,2.362) A6(-0.25,2.362) A7(0.25,2.362) A8(1.25,2.362) B5(1.75,2.362) B6(0.75,2.362) B7(-0.75,2.362) B8(-1.75,2.362)
  Board Outline Layer circle w0.005: c2.89,1.288 r0.325
  Board Outline Layer circle w0.005: c-2.89,1.288 r0.325
  Board Outline Layer region: 3.215,1.288 3.183,1.147 3.093,1.034 2.962,0.971 2.818,0.971 2.687,1.034 2.597,1.147 2.565,1.288 2.565,1.288 2.597,1.429 2.687,1.542 2.818,1.605 2.962,1.605 3.093,1.542 3.183,1.429 3.215,1.288
  Board Outline Layer region: -2.565,1.288 -2.597,1.147 -2.687,1.034 -2.818,0.971 -2.962,0.971 -3.093,1.034 -3.183,1.147 -3.215,1.288 -3.215,1.288 -3.183,1.429 -3.093,1.542 -2.962,1.605 -2.818,1.605 -2.687,1.542 -2.597,1.429 -2.565,1.288
  Multi-Layer board cut-out: 3.215,1.288 3.183,1.147 3.093,1.034 2.962,0.971 2.818,0.971 2.687,1.034 2.597,1.147 2.565,1.288 2.565,1.288 2.597,1.429 2.687,1.542 2.818,1.605 2.962,1.605 3.093,1.542 3.183,1.429 3.215,1.288
  Multi-Layer board cut-out: -2.565,1.288 -2.597,1.147 -2.687,1.034 -2.818,0.971 -2.962,0.971 -3.093,1.034 -3.183,1.147 -3.215,1.288 -3.215,1.288 -3.183,1.429 -3.093,1.542 -2.962,1.605 -2.818,1.605 -2.687,1.542 -2.597,1.429 -2.565,1.288
  silkscreen extent -4.45,-5 4.45,0.52
WIRELM-SMD_ESP32-S3-WROOM-1 [mm]
  rect 1.5x0.9 smd: 1(-8.75,8.895) 2(-8.75,7.625) 3(-8.75,6.355) 4(-8.75,5.085) 5(-8.75,3.815) 6(-8.75,2.545) 7(-8.75,1.275) 8(-8.75,0.005) 9(-8.75,-1.265) 10(-8.75,-2.535) 11(-8.75,-3.805) 12(-8.75,-5.075) 13(-8.75,-6.345) 14(-8.75,-7.615) 27(8.75,-7.615) 28(8.75,-6.345) 29(8.75,-5.075) 30(8.75,-3.805) 31(8.75,-2.535) 32(8.75,-1.265) 33(8.75,0.005) 34(8.75,1.275) 35(8.75,2.545) 36(8.75,3.815) 37(8.75,5.085) 38(8.75,6.355) 39(8.75,7.625) 40(8.75,8.895)
  rect 0.9x1.5 smd: 15(-6.985,-8.895) 16(-5.715,-8.895) 17(-4.445,-8.895) 18(-3.175,-8.895) 19(-1.905,-8.895) 20(-0.635,-8.895) 21(0.635,-8.895) 22(1.905,-8.895) 23(3.175,-8.895) 24(4.445,-8.895) 25(5.715,-8.895) 26(6.985,-8.865)
  rect 0.9x0.9 smd: 41(-2.9,-0.225) 41(-2.9,1.175) 41(-2.9,2.575) 41(-1.5,2.575) 41(-1.5,-0.225) 41(-1.5,1.175) 41(-0.1,2.575) 41(-0.1,1.175) 41(-0.1,-0.225)
  silkscreen extent -9,-9.14 9.02,16.39

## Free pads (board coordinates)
  round 1.524 hole 0.914: 1(94.996,103.632) 1(105.918,126.746)
  round 0.08 smd: 55(90.8,126.56) 55(91.821,126.238) 55(92.679,156.358) 55(92.71,96.012) 55(92.71,125.857) 55(94.723,92.475) 55(94.742,91.567) 55(97.282,142.367) 55(120.39,102.962) 55(121.87,104.992) 55(139.106,101.161) 55(140.506,101.121)
  round 0.08 smd far side: 55(100.711,126.619) 55(107.315,135.742) 55(108.458,135.763) 55(108.585,147.574) 55(109.093,136.525)

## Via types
v1: diameter 0.4, hole 0.3, Top Layer to Bottom Layer, 311 vias
v2: diameter 1, hole 0.5, Top Layer to Bottom Layer, 12 vias
v3: diameter 0.5, hole 0.3, Top Layer to Bottom Layer, 3 vias

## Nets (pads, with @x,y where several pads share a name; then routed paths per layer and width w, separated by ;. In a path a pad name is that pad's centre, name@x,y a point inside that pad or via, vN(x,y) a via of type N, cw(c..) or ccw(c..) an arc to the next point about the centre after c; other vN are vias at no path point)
$1N9437: R1.1 U5.37 | length 2.5
  Top Layer w0.254: R1.1@132.207,159.333 132.994,158.546 U5.37@132.994,157.153
$1N11348: R2.1 U5.38 | length 19.3
  Top Layer w0.1: R2.1@115.368,152.654 128.651,152.654 132.207,156.21 132.207,157.14 U5.38@132.194,157.153
$1N11975: R7.1 U2.3 | length 1.5
  Top Layer w0.254: U2.3@93.467,107.201 93.472,107.196 R7.1@93.472,105.716
$1N12553: R10.2 USB1.B5 | length 1.7
  Top Layer w0.254: USB1.B5@89.103,94.516 90.334,94.516 R10.2@90.687,94.869
$1N12557: R9.2 USB1.A5 | length 2
  Top Layer w0.254: USB1.A5@89.103,97.516 90.141,97.516 R9.2@90.805,98.18
$1N14416: C18.2 L1.1 U6.5 | length 7.6
  Top Layer w0.254: L1.1@94.663,96.266 94.663,98.425 94.234,98.854 94.234,101.506 94.516,101.789 94.736,101.789 C18.2@94.742,101.795 96.254,101.795 U6.5@96.313,101.854
$1N14459: C18.1 U6.6 | length 1.8
  Top Layer w0.254: C18.1@94.742,101.405 95.243,100.904 U6.6@96.313,100.904
$1N14567: C19.1 R11.1 R12.2 U6.1 | length 11.6
  Top Layer w0.254: U6.1@99.013,100.904 102.996,100.904 C19.1@104.14,99.76 107.135,99.76 R11.1@107.188,99.813 110.092,99.813 R12.2@110.109,99.831
$1N16832: C24.2 L2.1 U7.5 | length 5.3
  Top Layer w0.254: C24.2@128.524,103.056 127.703,102.235 U7.5@127.207,102.235 127.213,102.229 L2.1@130.842,102.229
$1N16833: C24.1 U7.6 | length 1.4
  Top Layer w0.254: U7.6@127.207,103.185 127.462,103.44 128.518,103.44 C24.1@128.524,103.446
$1N16834: C25.1 R14.2 R15.1 U7.1 | length 30.7
  Top Layer w0.254: U7.1@124.507,103.185 124.802,103.185 125.857,102.13 125.857,101.39 134.156,93.091 141.224,93.091 142.092,93.959 R14.2@142.092,97.711 141.076,97.711 R15.1@140.56,97.194 140.506,97.141 C25.1@140.506,94.527
$1N17349: C29.2 C30.2 C31.1 C32.1 | length 3.8
  Top Layer w0.254: C30.2@122.75,108.458 123.825,107.383 C32.1@123.825,106.082 122.914,106.082 C29.2@122.877,106.045
$1N29790: R26.2 U2.5 | length 57.9
  Top Layer w0.1: v1(83.558,147.32) 83.82,147.582 R26.2@83.82,148.157 ; U2.5@96.007,107.201 96.012,107.196 v1(96.012,106.172)
  Bottom Layer w0.1: v1(83.558,147.32) 83.439,147.201 83.439,146.888 83.31,146.76 83.31,146.488 83.439,146.36 83.439,146.088 83.31,145.96 83.31,145.688 83.439,145.56 83.439,145.288 83.31,145.16 83.31,144.888 83.439,144.76 83.439,144.488 83.31,144.36 83.31,144.088 83.439,143.96 83.439,143.688 83.31,143.56 83.31,143.288 83.439,143.16 83.439,142.888 83.31,142.76 83.31,142.488 83.439,142.36 83.439,105.283 83.693,105.029 93.471,105.029 94.614,106.172 v1(96.012,106.172)
$1N29833: R27.2 U2.6 | length 59.2
  Top Layer w0.1: v1(84.237,147.284) 84.237,147.431 R27.2@84.963,148.157 ; v1(97.277,106.172) U2.6@97.277,107.201
  Bottom Layer w0.1: v1(84.237,147.284) 83.947,146.994 83.947,146.723 83.876,146.652 83.739,146.652 83.668,146.582 83.668,146.323 83.739,146.252 83.876,146.252 83.947,146.182 83.947,145.923 83.876,145.852 83.739,145.852 83.668,145.782 83.668,145.523 83.739,145.452 83.876,145.452 83.947,145.382 83.947,145.123 83.876,145.052 83.739,145.052 83.668,144.982 83.668,144.723 83.739,144.652 83.876,144.652 83.947,144.582 83.947,144.323 83.876,144.252 83.739,144.252 83.668,144.182 83.668,143.923 83.739,143.852 83.876,143.852 83.947,143.782 83.947,143.523 83.876,143.452 83.739,143.452 83.668,143.382 83.668,143.123 83.739,143.052 83.876,143.052 83.947,142.982 83.947,142.723 83.876,142.652 83.739,142.652 83.668,142.582 83.668,142.323 83.739,142.252 83.876,142.252 83.947,142.182 83.947,141.923 83.876,141.852 83.739,141.852 83.668,141.782 83.668,141.523 83.739,141.452 83.876,141.452 83.947,141.382 83.947,141.159 83.876,141.088 83.739,141.088 83.668,141.018 83.668,140.759 83.739,140.688 83.876,140.688 83.947,140.618 83.947,140.359 83.876,140.288 83.739,140.288 83.668,140.218 83.668,139.959 83.739,139.888 83.876,139.888 83.947,139.818 83.947,139.559 83.876,139.488 83.739,139.488 83.668,139.418 83.668,139.159 83.739,139.088 83.876,139.088 83.947,139.018 83.947,108.712 85.725,106.934 96.515,106.934 v1(97.277,106.172)
$1N29916: R29.2 U2.9 | length 59.1
  Top Layer w0.1: v1(85.548,147.116) 85.903,147.116 86.945,148.157 R29.2@87.249,148.157 ; v1(99.695,108.966) 101.087,107.574 U2.9@101.087,107.201
  Bottom Layer w0.1: v1(85.548,147.116) 85.346,146.914 85.29,146.914 85.017,146.641 85.017,146.344 85.088,146.274 85.273,146.274 85.344,146.203 85.344,145.944 85.273,145.874 85.088,145.874 85.017,145.803 85.017,145.544 85.088,145.474 85.273,145.474 85.344,145.403 85.344,145.144 85.273,145.074 85.088,145.074 85.017,145.003 85.017,144.744 85.088,144.674 85.273,144.674 85.344,144.603 85.344,144.344 85.273,144.274 85.088,144.274 85.017,144.203 85.017,143.944 85.088,143.874 85.273,143.874 85.344,143.803 85.344,143.544 85.273,143.474 85.088,143.474 85.017,143.403 85.017,143.144 85.088,143.074 85.273,143.074 85.344,143.003 85.344,142.744 85.273,142.674 85.088,142.674 85.017,142.603 85.017,142.389 85.088,142.319 85.273,142.319 85.344,142.248 85.344,141.989 85.273,141.919 85.088,141.919 85.017,141.848 85.017,141.589 85.088,141.519 85.273,141.519 85.344,141.448 85.344,141.189 85.273,141.119 85.088,141.119 85.017,141.048 85.017,112.214 88.265,108.966 v1(99.695,108.966)
$1N29959: R30.2 U2.12 | length 59.5
  Top Layer w0.1: v1(86.487,147.066) 87.301,147.066 R30.2@88.392,148.157 ; v1(97.028,110.49) 103.886,110.49 104.897,109.479 U2.12@104.897,107.201
  Bottom Layer w0.1: v1(86.487,147.066) 86.067,147.066 85.715,146.714 85.715,146.704 85.671,146.66 85.671,113.719 88.9,110.49 v1(97.028,110.49)
$1N30002: R31.2 U2.23 | length 58.9
  Top Layer w0.1: v1(86.868,120.142) 106.68,120.142 107.696,119.126 U2.23@108.59,119.126 ; v1@87.757,147.066 88.444,147.066 R31.2@89.535,148.157
  Bottom Layer w0.1: v1(86.868,120.142) 86.272,120.738 86.272,136.076 86.201,136.147 85.971,136.147 85.9,136.217 85.9,136.476 85.971,136.547 86.201,136.547 86.272,136.617 86.272,136.876 86.201,136.947 85.971,136.947 85.9,137.017 85.9,137.276 85.971,137.347 86.201,137.347 86.272,137.417 86.272,137.676 86.201,137.747 85.971,137.747 85.9,137.817 85.9,138.076 85.971,138.147 86.201,138.147 86.272,138.217 86.272,138.476 86.201,138.547 85.971,138.547 85.9,138.617 85.9,138.876 85.971,138.947 86.201,138.947 86.272,139.017 86.272,139.276 86.201,139.347 85.971,139.347 85.9,139.417 85.9,139.676 85.971,139.747 86.201,139.747 86.272,139.817 86.272,140.076 86.201,140.147 85.971,140.147 85.9,140.217 85.9,140.476 85.971,140.547 86.201,140.547 86.272,140.617 86.272,140.876 86.201,140.947 85.971,140.947 85.9,141.017 85.9,141.276 85.971,141.347 86.201,141.347 86.272,141.417 86.272,141.676 86.201,141.747 85.971,141.747 85.9,141.817 85.9,142.076 85.971,142.147 86.201,142.147 86.272,142.217 86.272,142.476 86.201,142.547 85.971,142.547 85.9,142.617 85.9,142.876 85.971,142.947 86.201,142.947 86.272,143.017 86.272,143.276 86.201,143.347 85.971,143.347 85.9,143.417 85.9,143.676 85.971,143.747 86.201,143.747 86.272,143.817 86.272,144.614 85.871,145.015 85.871,146.298 86.15,146.577 86.999,146.577 87.432,147.01 v1(87.813,147.01)
$1N30085: R34.2 U2.25 | length 59.4
  Top Layer w0.1: v1@89.916,146.812 90.603,146.812 91.821,148.03 R34.2@91.821,148.157 ; v1(90.424,121.793) 90.551,121.666 91.359,121.666 91.43,121.737 91.43,121.976 91.501,122.047 91.759,122.047 91.83,121.976 91.83,121.737 91.901,121.666 92.159,121.666 92.23,121.737 92.23,121.976 92.301,122.047 92.559,122.047 92.63,121.976 92.63,121.737 92.701,121.666 92.959,121.666 93.03,121.737 93.03,121.976 93.101,122.047 93.359,122.047 93.43,121.976 93.43,121.737 93.501,121.666 93.759,121.666 93.83,121.737 93.83,121.976 93.901,122.047 94.159,122.047 94.23,121.976 94.23,121.737 94.301,121.666 94.559,121.666 94.63,121.737 94.63,121.976 94.701,122.047 94.959,122.047 95.03,121.976 95.03,121.737 95.101,121.666 U2.25@108.59,121.666
  Bottom Layer w0.1: v1(89.909,146.819) 87.884,144.795 87.884,144.474 87.955,144.403 88.321,144.403 88.392,144.333 88.392,144.074 88.321,144.003 87.955,144.003 87.884,143.933 87.884,143.674 87.955,143.603 88.311,143.603 88.382,143.533 88.382,143.274 88.311,143.203 87.955,143.203 87.884,143.133 87.884,142.874 87.955,142.803 88.32,142.803 88.391,142.733 88.391,142.474 88.32,142.403 87.955,142.403 87.884,142.333 87.884,142.074 87.955,142.003 88.311,142.003 88.382,141.933 88.382,141.674 88.311,141.603 87.955,141.603 87.884,141.533 87.884,141.274 87.955,141.203 88.356,141.203 88.426,141.133 88.426,140.874 88.356,140.803 87.955,140.803 87.884,140.733 87.884,140.474 87.955,140.403 88.383,140.403 88.453,140.333 88.453,140.074 88.383,140.003 87.955,140.003 87.884,139.933 87.884,139.674 87.955,139.603 88.428,139.603 88.498,139.533 88.498,139.274 88.428,139.203 87.955,139.203 87.884,139.133 87.884,138.919 87.955,138.848 88.434,138.848 88.505,138.777 88.505,138.519 88.434,138.448 87.955,138.448 87.884,138.377 87.884,138.119 87.955,138.048 88.434,138.048 88.505,137.977 88.505,137.719 88.434,137.648 87.955,137.648 87.576,137.269 87.576,124.641 v1(90.424,121.793)
$1N30089: R32.2 U2.24 | length 59.6
  Top Layer w0.1: v1(88.9,146.939) 89.46,146.939 R32.2@90.678,148.157 ; v1(90.17,121.158) 106.553,121.158 107.315,120.396 U2.24@108.59,120.396
  Bottom Layer w0.1: v1(88.9,146.939) 88.338,146.377 87.337,146.377 86.741,145.781 86.741,144.049 86.812,143.979 87.305,143.979 87.376,143.908 87.376,143.649 87.305,143.579 86.812,143.579 86.741,143.508 86.741,143.249 86.812,143.179 87.305,143.179 87.376,143.108 87.376,142.849 87.305,142.779 86.812,142.779 86.741,142.708 86.741,142.449 86.812,142.379 87.305,142.379 87.376,142.308 87.376,142.049 87.305,141.979 86.812,141.979 86.741,141.908 86.741,141.649 86.812,141.579 87.305,141.579 87.376,141.508 87.376,141.249 87.305,141.179 86.812,141.179 86.741,141.108 86.741,140.849 86.812,140.779 87.305,140.779 87.376,140.708 87.376,140.449 87.305,140.379 86.812,140.379 86.741,140.308 86.741,140.049 86.812,139.979 87.305,139.979 87.376,139.908 87.376,139.649 87.305,139.579 86.812,139.579 86.741,139.508 86.741,139.249 86.812,139.179 87.305,139.179 87.376,139.108 87.376,138.849 87.305,138.779 86.812,138.779 86.741,138.708 86.741,138.449 86.812,138.379 87.305,138.379 87.376,138.308 87.376,138.049 87.305,137.979 86.812,137.979 86.741,137.908 86.741,137.649 86.812,137.579 87.305,137.579 87.376,137.508 87.376,137.249 87.305,137.179 86.812,137.179 86.741,137.108 86.741,124.587 v1(90.17,121.158)
$1N30093: R28.2 U2.7 | length 59.1
  Top Layer w0.1: v1(84.869,147.193) 84.93,147.193 85.895,148.157 R28.2@86.106,148.157 ; U2.7@98.547,107.201 v1(98.547,108.204)
  Bottom Layer w0.1: v1(84.869,147.193) 84.201,146.525 84.201,146.281 84.272,146.21 84.384,146.21 84.455,146.139 84.455,145.881 84.384,145.81 84.272,145.81 84.201,145.739 84.201,145.481 84.272,145.41 84.384,145.41 84.455,145.339 84.455,145.081 84.384,145.01 84.272,145.01 84.201,144.939 84.201,144.681 84.272,144.61 84.384,144.61 84.455,144.539 84.455,144.281 84.384,144.21 84.272,144.21 84.201,144.139 84.201,143.881 84.272,143.81 84.384,143.81 84.455,143.739 84.455,143.481 84.384,143.41 84.272,143.41 84.201,143.339 84.201,143.081 84.272,143.01 84.384,143.01 84.455,142.939 84.455,142.681 84.384,142.61 84.272,142.61 84.201,142.539 84.201,142.281 84.272,142.21 84.384,142.21 84.455,142.139 84.455,141.881 84.384,141.81 84.272,141.81 84.201,141.739 84.201,141.481 84.272,141.41 84.384,141.41 84.455,141.339 84.455,141.081 84.384,141.01 84.272,141.01 84.201,140.939 84.201,140.689 84.272,140.618 84.511,140.618 84.582,140.547 84.582,140.289 84.511,140.218 84.272,140.218 84.201,140.147 84.201,139.889 84.272,139.818 84.511,139.818 84.582,139.747 84.582,139.489 84.511,139.418 84.272,139.418 84.201,139.347 84.201,109.474 85.471,108.204 v1(98.547,108.204)
$1N33205: P1.8 R35.1 | length 1.9
  Top Layer w0.1: R35.1@115.57,173.153 115.611,173.193 P1.8@115.611,175.02
$1N60668: C64.1 U11.6 | length 1.4
  Top Layer w0.1: U11.6@110.242,94.902 110.94,95.6 110.94,95.625 111.058,95.743 111.083,95.743 111.166,95.826 C64.1@111.252,95.826
$1N60669: C64.2 L3.1 U11.5 | length 3.6
  Top Layer w0.1: U11.5@110.242,93.952 L3.1@111.918,93.952 ; C64.2@111.252,95.436 111.252,94.618 L3.1@111.918,93.952 ; L3.1@112.017,93.853 L3.1@111.918,93.952
$1N60670: C65.1 R40.2 R41.1 U11.1 | length 8
  Top Layer w0.1: U11.1@107.542,94.902 108.298,94.902 109.102,94.098 R40.2@109.102,88.011
$1N63749: R43.1 USB2.A5 | length 6.1
  Top Layer w0.1: R43.1@97.781,89.535 97.908,89.408 v1(98.679,89.408) ; v1(102.255,90.551) USB2.A5@102.255,91.643
  Bottom Layer w0.1: v1(98.679,89.408) 101.112,89.408 v1(102.255,90.551)
$1N63772: R42.1 USB2.B5 | length 10.5
  Top Layer w0.1: R42.1@97.781,88.011 98.552,88.011 v1(98.679,88.138) ; USB2.B5@105.255,91.643 105.283,91.616 v1(105.283,90.678)
  Bottom Layer w0.1: v1(98.679,88.138) 99.441,88.9 105.029,88.9 105.057,88.928 105.057,90.452 v1(105.283,90.678)
$1N63825: R44.2 USB2.A4B9 USB2.B4A9 | length 12.3
  Top Layer w0.1: USB2.A4B9@101.105,91.643 101.346,91.402 v1(101.346,90.424) 101.785,89.985 105.606,89.985 105.868,90.247 105.868,91.606 USB2.B4A9@105.905,91.643 ; v1(102.235,93.726) 103.115,93.726 R44.2@103.251,93.862
  Bottom Layer w0.1: v1(101.346,90.424) 101.346,92.837 v1(102.235,93.726)
$1N64401: C69.2 L4.1 U12.5 | length 3.6
  Top Layer w0.1: C69.2@124.782,92.964 125.479,92.267 L4.1@125.479,91.186
  Top Layer w0.5: U12.5@123.905,91.186 L4.1@125.479,91.186
$1N64402: C69.1 U12.6 | length 1
  Top Layer w0.1: U12.6@123.905,92.136 124.392,92.623 C69.1@124.392,92.964
$1N64403: C70.1 R46.2 R47.1 U12.1 | length 10.6
  Top Layer w0.1: R46.2@119.625,86.995 121.093,86.995 C70.1@121.22,87.122 ; U12.1@121.205,92.136 121.266,92.075 121.452,92.075 121.957,91.57 121.957,89.852 121.22,89.115 C70.1@121.22,87.122 ; R47.1@124.154,86.36 121.982,86.36 C70.1@121.22,87.122
$2N5507: R23.2 U1.P10 | length 20
  Top Layer w0.1: R23.2@89.714,150.495 92.329,150.495 92.435,150.389 92.435,150.201 93.051,149.585 95.271,149.585 v1(95.631,149.225)
  Top Layer w0.254: U1.P10@107.753,148.254 108.077,148.578 v1@108.077,148.59
  Bottom Layer w0.254: v1(95.631,149.225) 95.989,149.583 106.038,149.583 106.91,148.711 107.617,148.711 107.717,148.611 v1(108.098,148.611)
